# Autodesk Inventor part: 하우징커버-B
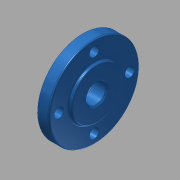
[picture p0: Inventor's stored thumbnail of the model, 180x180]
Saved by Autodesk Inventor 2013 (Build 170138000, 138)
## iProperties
Created: 2018-01
Part Number: 하우징커버-B
Material: 알루미늄 6061
Document SubType Name: Modeling
Designer: mduedu
Density: 1 g/cm^3
Author: mduedu
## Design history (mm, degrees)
sketch "스케치1"
  geometry: C1 r 16 at (0, 0); 1 further point
  constraints: 1 centre point, 1 coincident
  dimensions: "d0" = 32 diameter of C1
extrude "돌출1" new body sketch "스케치1" distance "d1" = 4; taper "d2" = 0 deg
sketch "스케치2"
  geometry: C1 r 9 at (0, 0); 1 further point
  constraints: 1 centre point, 1 coincident
  dimensions: "d3" = 18 diameter of C1
extrude "돌출2" join sketch "스케치2" distance "d4" = 1; taper "d5" = 0 deg
fillet "모깎기1" dims "d6" = 0.5
fillet "모깎기2" dims "d7" = 0.5
hole "구멍1" diameter "d10" = 7; stored, may be unused: countersink angle "d14" = 90 deg, drill point angle "d16" = 118 deg; dims "d8" = 10, "d9" = 10, "d11" = 6, "d12" = 4, "d13" = 2, "d15" = 8
chamfer "모따기1" distance "d17" = 0.5; stored, may be unused: second distance "d18" = 2, angle "d19" = 45 deg
sketch "스케치3" dims "d21" = 25
  geometry: 6 further points
  constraints: 2 vertical alignment, 1 coincident, 7 other
  dimensions: "d24" = 360 deg dimension on point (0, 0) point (0, 12.5) (derived)
sketch "스케치4"
  geometry: 4 further points
  constraints: 4 other
hole "구멍2" sketch "스케치4" at (-12.5, 0), (0, -12.5), (12.5, 0), (0, 12.5) diameter "d26" = 3.4; stored, may be unused: countersink angle "d30" = 90 deg, drill point angle "d32" = 0 deg; dims "d27" = 6, "d28" = 4, "d29" = 2, "d31" = 8
node "솔리드1"
